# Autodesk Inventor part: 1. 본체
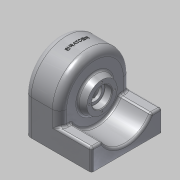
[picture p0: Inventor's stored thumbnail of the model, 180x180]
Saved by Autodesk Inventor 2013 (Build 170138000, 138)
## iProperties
Created: 2015-02
Part Number: 1. 본체
Material: 알루미늄 6061
Document SubType Name: Modeling
Designer: Administrator
Density: 2.71 g/cm^3
Mass: 575.526 g
Surface Area: 706.56 cm^2
Volume: 212.371 cm^3
Author: Administrator
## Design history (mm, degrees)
sketch "스케치1"
  geometry: L1 (-25, 50)-(25, 50); L2 (25, 50)-(25, -50); L3 (25, -50)-(-25, -50); L4 (-25, -50)-(-25, 50); 3 further points
  constraints: 8 end point, 2 midpoint, 2 parallel, 1 horizontal, 1 horizontal alignment, 1 perpendicular, 1 vertical alignment
  dimensions: "d0" = 50 distance of L2.end L3.end; "d2" = 100 distance of L1.end L2.end
extrude "돌출1" new body sketch "스케치1" distance "d3" = 100; taper "d4" = 0 deg
fillet "모깎기1" dims "d5" = 50
sketch "스케치5"
  geometry: L1 (-35, 50)-(34, 50); L2 (-35, 50)-(-35, 71.36); L3 (-35, 71.36)-(-25, 75); L4 (-25, 50)-(-25, 100) reference; L5 (-25, 0)-(-25, 50) reference; L6 (25, 0)-(25, 50) reference; L7 (-25, 0)-(25, 0) reference; L8 (-25, 70)-(34, 70); L9 (34, 50)-(34, 70); L10 (-25, 75)-(-25, 75); L11 (-25, 75)-(-25, 70); 1 further point
  constraints: 14 end point, 4 perpendicular, 1 horizontal, 1 midpoint, 1 parallel, 1 point on line
  dimensions: "d28" = 10 distance from line of L5 L1.start; "d29" = 9 distance from line of L6 L1.end; "d30" = 50 distance between parallel lines of L7 L1; "d31" = 110 deg angle of L3 L4; "d32" = 50 diameter of L3.end L1; "d33" = 40 diameter of L8 L1
revolve "회전1" sketch "스케치5" stored, may be unused: angle "d34" = 90 deg
node "작업 평면1"
sketch "스케치6"
  geometry: L1 (0, 100)-(50, 100) reference; L2 (0, 0)-(50, 0) reference; L3 (0, 100)-(0, 0) reference; L4 (50, 4)-(0, 4); L5 (0, 96)-(50, 96); L6 (0, 96)-(0, 4); A1 r 50 centre (50, 50) between (50, 0) and (50, 100) reference; A2 r 46 centre (50, 50) between (50, 4) and (50, 96); 1 further point
  constraints: 6 end point, 2 point on circle, 2 point on line, 1 centre point, 1 collinear
  dimensions: "d35" = 4 radial gap between concentric circles of A1 A2; "d36" = 4 distance between parallel lines of L1 L5; "d37" = 4 distance between parallel lines of L2 L4
extrude "돌출3" cut sketch "스케치6" stored distance "d38" = 42; taper "d39" = 0 deg
hole "구멍1" diameter "d42" = 20; stored, may be unused: countersink angle "d46" = 90 deg, drill point angle "d48" = 0 deg; dims "d40" = 10, "d41" = 10, "d43" = 6, "d44" = 28, "d45" = 10, "d47" = 4
hole "구멍2" diameter "d51" = 20; stored, may be unused: countersink angle "d55" = 90 deg, drill point angle "d57" = 0 deg; dims "d49" = 10, "d50" = 10, "d52" = 6, "d53" = 28, "d54" = 8, "d56" = 2
sketch "스케치7"
  geometry: L1 (0, 0)-(-50, 0) reference; L2 (0, 100)-(0, 0) reference; L3 (0, 100)-(-50, 100) reference; L4 (-30, 100)-(0, 100); L5 (-30, 100)-(-30, 84.641); L6 (0, 0)-(-30, 0); L7 (-30, 0)-(-30, 15.359); A1 r 50 centre (-50, 50) between (-50, 100) and (-50, 0) reference; A2 r 40 centre (-50, 50) between (-30, 15.359) and (-30, 84.641); 1 further point
  constraints: 8 end point, 2 collinear, 2 perpendicular, 2 point on circle, 2 point on line, 1 centre point, 1 coincident
  dimensions: "d58" = 80 diameter of A2; "d59" = 30 distance of L4.start L2.start
extrude "돌출4" join sketch "스케치7" distance "d60" = 45; taper "d61" = 0 deg
sketch "스케치8"
  geometry: L1 (-70, -50)-(-70, 50) reference; L2 (25, -50)-(25, 50) reference; L3 (-61, 41.75)-(-61, -41.75); 4 further points
  constraints: 3 horizontal alignment, 2 end point, 2 vertical alignment, 1 midpoint, 1 parallel
  dimensions: "d62" = 33 distance of point (-28, 41.75) L3.start; "d64" = 9 distance from line of L1 L3.start; "d65" = 83.5 distance of L3.end L3.start
hole "구멍3" sketch "스케치8" at (-61, 41.75), (-28, 41.75), (-28, -41.75), (-61, -41.75) diameter "d66" = 5.134; stored, may be unused: countersink angle "d70" = 90 deg, drill point angle "d72" = 118 deg; dims "d67" = 10, "d68" = 4, "d69" = 2, "d71" = 13
sketch "스케치9" dims "d73" = 36
  geometry: C1 r 14 at (0, 0) reference; C2 r 21.36 at (0, 0) reference; 3 further points
  constraints: 2 horizontal alignment, 1 coincident, 2 other
hole "구멍4" sketch "스케치9" at (-18, 0) diameter "d74" = 2.459; stored, may be unused: countersink angle "d78" = 90 deg, drill point angle "d80" = 118 deg; dims "d75" = 6, "d76" = 4, "d77" = 2, "d79" = 9
fillet "모깎기2" dims "d84" = 10
fillet "모깎기3" dims "d85" = 6
fillet "모깎기4" dims "d86" = 0.3
fillet "모깎기5" dims "d87" = 3
chamfer "모따기1" distance "d88" = 1; stored, may be unused: second distance "d89" = 2, angle "d90" = 45 deg
node "작업 평면2"
sketch "스케치10"
  geometry: L1 (-2.5, 50)-(-2.5, -50) reference; L2 (-12.5, -40)-(-12.5, 40) reference; 3 further points
  constraints: 1 midpoint, 1 other
  dimensions: "d91" = 25 distance from line of point (12.5, 0) L2
feature "엠보싱1" sketch "스케치10" dims "d0" = 50, "d2" = 100, "d92" = 0.5, "d93" = 0
node "솔리드1"
pattern_circular "원형 패턴1" dims angle "d82" = 360 deg
